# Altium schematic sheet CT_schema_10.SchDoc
size 147 x 119 mm
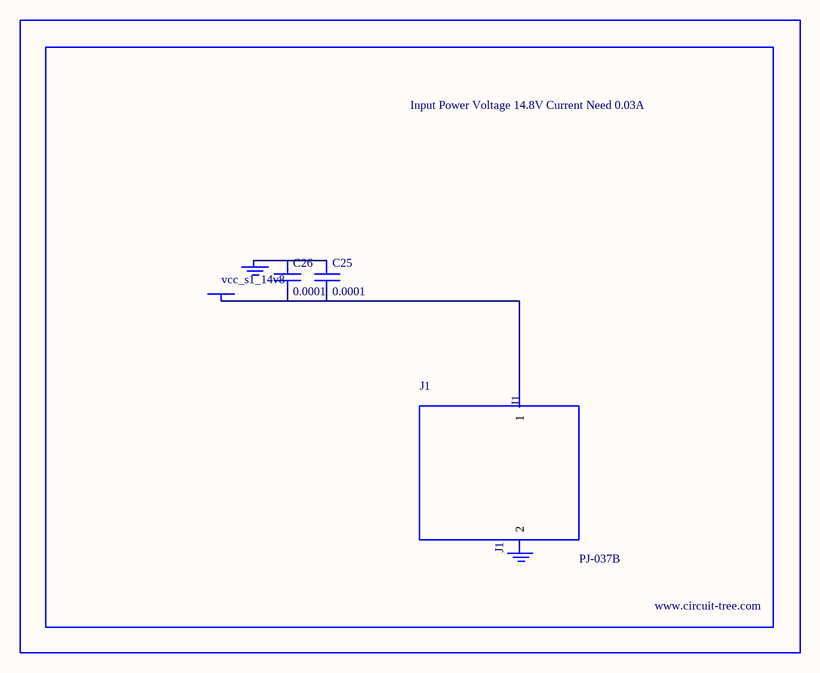
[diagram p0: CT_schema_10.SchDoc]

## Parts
BORDER9  (no value)
C25  0.0001  [EXV-9H]
C26  0.0001  [EXV-9H]
GND_INSTANCE_9_0  (no value)
GND_INSTANCE_9_1  (no value)
J1  PJ-037B  [PJ-037B_PACKAGE]
POWER_INSTANCE_9_0  vcc_s1_14v8

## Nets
NetC25_1: C25.1 C26.1 GND_INSTANCE_9_0.0(GND)
NetC25_2: C25.2 C26.2 J1.1 POWER_INSTANCE_9_0.0(PWR)

Not connected (* = marked no-connect by the designer): GND_INSTANCE_9_1 0(GND); J1 2

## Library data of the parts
BORDER9 = BORDER_PAGE9
C25 C26 = EDK107M035A9HAA
GND_INSTANCE_9_0 GND_INSTANCE_9_1 = GND
POWER_INSTANCE_9_0 = PWR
